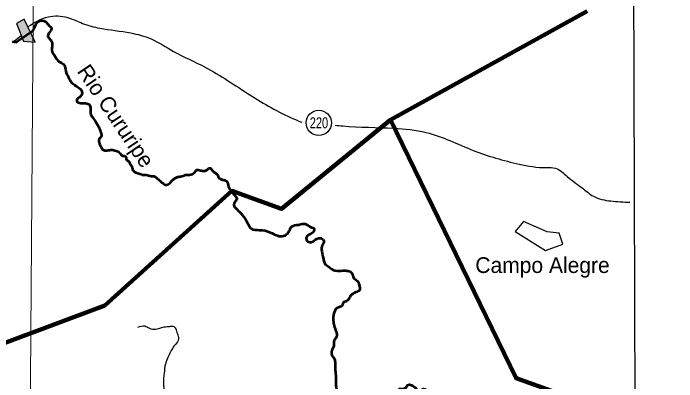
# Model space of a CAD drawing. Extents: x -1643653 to 4543381, y 1624270 to 13878484.
# Drawn here: x 773658 to 794759, y 8911096 to 8922804 of the extents above; entities that cross this region are included whole.
import ezdxf
from ezdxf.enums import TextEntityAlignment as Align

# ---------------------------------------------------------------- set-up
doc = ezdxf.new("R2010")
doc.units = 0
doc.header["$LTSCALE"] = 200
for name, color, linetype, lineweight in [('1', 7, 'Continuous', 13), ('12', 7, 'Continuous', 25), ('21', 7, 'Continuous', 25), ('24', 7, 'Continuous', 25), ('3', 7, 'Continuous', 13), ('48', 7, 'Continuous', 25), ('60', 7, 'Continuous', 13), ('9', 7, 'Continuous', 90)]:
    doc.layers.add(name, color=color, linetype=linetype, lineweight=lineweight)
doc.layers.add('41', color=7, linetype='Continuous')
doc.layers.add('49', color=7, linetype='Continuous')

msp = doc.modelspace()

# ---------------------------------------------------------------- hatches: boundary and pattern name
at = {"layer": '21'}
msp.add_hatch(color=256, dxfattribs=at).paths.add_polyline_path([(774002.3, 8922616.4), (773757.5, 8922483.3), (773979.6, 8921912.9), (774358.6, 8921888)])

# ---------------------------------------------------------------- linework, layer by layer
at = {"layer": '1'}
msp.add_lwpolyline([(774987.1, 9020818), (774482.3, 8948876), (774053.6, 8890875.3)], dxfattribs=at)
at = {"layer": '12'}
msp.add_lwpolyline([(773904.7, 8922082.2), (773628.7, 8921864.1)], dxfattribs=at)
for points in [[(774127.4, 8922381.7), (774762.8, 8922691.1), (775387.8, 8922672.2), (775861.3, 8922482.8), (776410.6, 8922331.3), (777395.4, 8922179.8), (778039.4, 8921990.4), (778759.1, 8921592.6), (779744, 8921100.2), (781183.4, 8920210), (782566, 8919452.4), (782831.5, 8919338.8)], [(783895.5, 8919249), (784138, 8919225.2), (785766.8, 8919149.4), (786789.5, 8919016.8), (788285.7, 8918448.6), (789744.1, 8918013), (790615.3, 8917899.4), (790899.4, 8917880.4), (791278.2, 8917615.3), (791751.7, 8917255.4), (792111.6, 8916990.3), (792660.8, 8916838.8), (793266.9, 8916800.9)]]:
    msp.add_spline(points, degree=3, dxfattribs=at)
at = {"layer": '21'}
for points in [[(774002.3, 8922616.4), (773757.5, 8922483.3), (773979.6, 8921912.9), (774358.6, 8921888)], [(789881.8, 8916188.9), (789618.2, 8915864.4), (790586.5, 8915270.3), (791137.2, 8915470.4), (791021.8, 8915819.8), (790643.3, 8915857.4)]]:
    msp.add_lwpolyline(points, close=True, dxfattribs=at)
at = {"layer": '24', "lineweight": 53}
msp.add_lwpolyline([(773624.7, 8921905.7), (773745.1, 8921884.1), (773825.5, 8921937.8), (774289.1, 8922253.7)], dxfattribs=at)
for points in [[(774289.1, 8922253.7), (774354.7, 8922391.4), (774442, 8922536.8), (774689.1, 8922536.8), (774790.9, 8922420.5), (774878.1, 8922333.3), (774790.9, 8922173.4), (774761.8, 8922071.6), (774878.1, 8921911.7), (774892.6, 8921751.8), (774892.6, 8921577.3), (774965.3, 8921461), (775110.7, 8921272), (775256.1, 8921184.8), (775328.8, 8920966.7), (775414.3, 8920761.6), (775502.1, 8920615.2), (775624.1, 8920512.8), (775785.1, 8920400.6), (775843.6, 8920312.7), (775833.9, 8920220.1), (775750.9, 8920122.5), (775692.4, 8920078.6), (775692.4, 8919990.8), (775765.6, 8919956.6), (775921.7, 8919946.9), (776063.2, 8919912.7), (776097.3, 8919868.8), (776116.8, 8919751.7), (776126.6, 8919585.9), (776175.3, 8919502.9), (776272.9, 8919366.3), (776394.9, 8919151.7), (776448.5, 8918990.7), (776453.4, 8918888.2), (776390, 8918800.4), (776385.1, 8918698), (776409.5, 8918619.9), (776448.5, 8918546.8), (776512, 8918463.8), (776633.9, 8918444.3), (776790, 8918468.7), (776926.6, 8918434.6), (777043.7, 8918366.2), (777116.9, 8918283.3), (777209.6, 8918263.8), (777243.7, 8918224.8), (777248.6, 8918166.2), (777326.7, 8918104.2), (777375.5, 8918011.4), (777424.2, 8917938.2), (777453.5, 8917840.6), (777512, 8917767.4), (777614.5, 8917723.5), (777760.8, 8917674.7)], [(777760.8, 8917674.7), (777931.6, 8917660), (778053.6, 8917630.7), (778136.5, 8917625.8), (778238.9, 8917557.5), (778356, 8917450.1), (778453.6, 8917376.9), (778536.5, 8917347.6), (778609.7, 8917381.8), (778702.4, 8917479.4), (778790.2, 8917552.6), (778868.2, 8917591.7), (778980.5, 8917621), (779063.4, 8917635.6), (779126.8, 8917669.8), (779224.4, 8917669.8), (779307.3, 8917679.5), (779375.6, 8917713.7), (779439, 8917767.4), (779497.6, 8917826), (779585.4, 8917816.2), (779702.5, 8917796.7), (779756.1, 8917796.7), (779843.9, 8917845.5), (779883, 8917879.7), (779931.7, 8917879.7), (779965.9, 8917835.7), (780029.3, 8917767.4), (780109.8, 8917713.7), (780163.5, 8917645.4), (780187.8, 8917586.8), (780236.6, 8917552.6), (780290.3, 8917523.3), (780392.7, 8917498.9), (780451.3, 8917459.9), (780485.4, 8917381.8), (780500.1, 8917293.9), (780548.8, 8917211), (780621.5, 8917109.9), (780695, 8917023.2), (780736.5, 8916974.2), (780766.6, 8916932.7), (780764.7, 8916906.3), (780717.6, 8916827.1), (780676.1, 8916734.8), (780679.9, 8916678.2), (780713.8, 8916634.8), (780774.2, 8916568.9), (780834.5, 8916512.3), (780885.4, 8916463.3), (780938.2, 8916401.1), (780996.6, 8916325.7), (781043.7, 8916254.1), (781083.3, 8916178.7), (781130.5, 8916097.6)], [(781130.5, 8916097.6), (781220, 8915963.8), (781483.9, 8915916.6), (781842.1, 8915841.2), (782058.9, 8915737.5), (782256.8, 8915728.1), (782407.6, 8915841.2), (782520.7, 8916029.7), (782737.5, 8916086.3), (782944.9, 8916114.6), (783124, 8916010.9), (783227.6, 8915954.3), (783142.8, 8915803.5), (783029.7, 8915747), (782982.6, 8915605.6), (783086.2, 8915530.2), (783274.8, 8915615), (783453.8, 8915652.7), (783538.7, 8915567.9), (783482.1, 8915435.9), (783472.7, 8915247.4), (783519.8, 8915002.3), (783557.5, 8914870.4), (783689.5, 8914747.8), (783896.8, 8914625.3), (784151.3, 8914625.3), (784311.6, 8914615.9), (784415.3, 8914559.3), (784490.7, 8914389.7), (784594.3, 8914304.8), (784660.3, 8914172.9), (784669.8, 8914003.2), (784509.5, 8913918.4), (784358.7, 8913786.4), (784255, 8913654.5), (784160.8, 8913616.8), (784123.1, 8913522.5), (783953.4, 8913437.7), (783846, 8913234), (783830, 8913084.7), (783856.7, 8912919.4), (783910, 8912732.8), (783942, 8912652.9), (783915.3, 8912477), (783862, 8912402.3), (783856.7, 8912343.7), (783851.3, 8912231.7), (783808.7, 8912141.1), (783776.7, 8912034.5), (783792.7, 8911938.5), (783851.3, 8911858.6), (783888.7, 8911757.3), (783894, 8911554.7), (783910, 8911357.5), (783915.3, 8911096.2)], [(783915.3, 8911096.2), (783936.7, 8910861.7), (783984.6, 8910696.4), (784053.9, 8910520.5), (784107.2, 8910355.2), (784176.5, 8910179.3), (784224.5, 8910056.7), (784293.8, 8909998.1), (784427.1, 8910040.7), (784592.4, 8910094), (784763, 8910190), (784858.9, 8910216.6), (785018.8, 8910168.7), (785141.5, 8910168.7), (785280.1, 8910253.9), (785429.3, 8910344.6), (785482.6, 8910451.2), (785557.3, 8910509.8), (785642.6, 8910499.2), (785786.5, 8910461.8), (785909.1, 8910451.2), (785951.8, 8910541.8), (785957.1, 8910621.8), (785866.5, 8910717.7), (785882.5, 8910829.7), (785946.4, 8910867), (786085, 8910872.3), (786154.3, 8910915), (786197, 8910984.3), (786324.9, 8910989.6), (786399.6, 8910947), (786495.5, 8910840.3), (786559.5, 8910765.7), (786612.8, 8910803), (786666.1, 8910851), (786751.4, 8910861.7), (786804.7, 8910787), (786783.4, 8910664.4), (786719.4, 8910616.4), (786623.5, 8910621.8), (786559.5, 8910531.2), (786532.8, 8910440.5), (786570.2, 8910371.2), (786676.8, 8910381.9), (786794.1, 8910413.9), (786868.7, 8910392.6), (786911.3, 8910317.9), (786954, 8910237.9), (787049.9, 8910158), (787049.9, 8910046), (787023.3, 8909960.7), (786895.3, 8909880.8), (786815.4, 8909822.1), (786762.1, 8909726.2), (786895.3, 8909621.1)]]:
    msp.add_spline(points, degree=3, dxfattribs=at)
at = {"layer": '24'}
msp.add_spline([(777617.6, 8912828.3), (777839.2, 8912869.9), (777991.6, 8912793.7), (778178.6, 8912766), (778455.7, 8912835.2), (778621.9, 8912856), (778760.5, 8912849.1), (778843.6, 8912745.2), (778864.3, 8912662.1), (778912.8, 8912502.8), (778850.5, 8912322.7), (778739.7, 8912191.1), (778663.5, 8912045.6), (778573.4, 8911865.5), (778497.2, 8911657.7), (778455.7, 8911366.8), (778434.9, 8911048.2), (778476.5, 8910750.4), (778518, 8910535.6), (778545.7, 8910341.7), (778580.4, 8910189.3), (778649.6, 8910085.4), (778732.8, 8909960.8), (778871.3, 8909884.6), (779051.4, 8909787.6), (779210.7, 8909787.6), (779356.1, 8909773.7), (779453.1, 8909759.9), (779598.6, 8909621.3), (779695.5, 8909496.7), (779834.1, 8909316.6), (779917.2, 8909178.1), (780007.2, 8909053.4), (780007.2, 8908921.8), (780009.3, 8908822.2), (780018.8, 8908742.2), (780037.6, 8908666.9), (780056.4, 8908582.2), (780110.5, 8908518.7), (780178.7, 8908476.4), (780303.4, 8908427), (780439.8, 8908424.6), (780552.7, 8908419.9), (780618.6, 8908419.9), (780740.9, 8908452.8), (780832.7, 8908471.7), (780938.5, 8908495.2), (781042, 8908518.7), (781150.2, 8908521.1), (781263.2, 8908495.2), (781387.8, 8908429.3), (781472.5, 8908377.6), (781569, 8908323.5), (781672.5, 8908252.9), (781759.5, 8908175.3)], degree=3, dxfattribs=at)
at = {"layer": '3', "lineweight": 25}
msp.add_lwpolyline([(563033.9, 9026438.8), (793061.1, 9026438.8), (793495.6, 8889836.8), (563468.3, 8889836.8)], close=True, dxfattribs=at)
at = {"layer": '48'}
msp.add_circle((783373.6, 8919321.2), 401.3, dxfattribs=at)
at = {"layer": '60', "lineweight": 25}
msp.add_spline([(814781, 9009175.5), (814787.2, 9009173.4), (814796.9, 9009173.4), (814799.4, 9009172.4), (814805.1, 9009174.5), (814805.6, 9009176.5), (814811.7, 9009179.5), (814811.7, 9009179.5), (814801.5, 9009181), (814790.7, 9009181.5), (814784.1, 9009183.1), (814777.4, 9009185.1), (814778.4, 9009175.5)], degree=3, dxfattribs=at)
at = {"layer": '9'}
for points in [[(765974.5, 8912469.6), (771548.8, 8911642.3), (776566.8, 8913518.4), (780614.1, 8917160.1), (782189.6, 8916587.3), (785656.2, 8919415.9), (791912, 8922868)], [(791729.4, 8903866.6), (792965.2, 8905190), (791720, 8910472.8), (789649.4, 8911206.9), (785656.2, 8919415.9)], [(791729.4, 8903866.6), (792965.2, 8905190), (791720, 8910472.8), (789649.4, 8911206.9), (785656.2, 8919415.9)]]:
    msp.add_lwpolyline(points, dxfattribs=at)

# ---------------------------------------------------------------- texts
at = {"layer": '41'}
msp.add_text('Campo Alegre', height=500, dxfattribs=at).set_placement((788354.2, 8914551.4))
at = {"layer": '48', "width": 0.75}
msp.add_text('220', height=350, dxfattribs=at).set_placement((783380.2, 8919147.9), align=Align.CENTER)
at = {"layer": '49'}
msp.add_text('Rio Cururipe', height=500, rotation=303.874, dxfattribs=at).set_placement((776713.2, 8919402.4), align=Align.CENTER)

doc.saveas('drawing.dxf')
